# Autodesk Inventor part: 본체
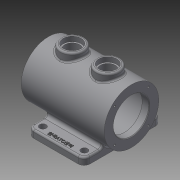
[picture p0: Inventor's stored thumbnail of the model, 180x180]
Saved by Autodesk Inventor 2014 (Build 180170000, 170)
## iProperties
Created: 2014-12
Part Number: 본체
Material: 일반
Document SubType Name: Modeling
Designer: Owner
Density: 1 g/cm^3
Appearance: 기본값
Author: Owner
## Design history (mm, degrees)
sketch "스케치1"
  geometry: L1 (-47.5, 65)-(47.5, 65); L2 (47.5, 65)-(47.5, -65); L3 (47.5, -65)-(-47.5, -65); L4 (-47.5, -65)-(-47.5, 65); 3 further points
  constraints: 8 end point, 2 midpoint, 2 parallel, 1 horizontal, 1 horizontal alignment, 1 perpendicular, 1 vertical alignment
  dimensions: "d0" = 95 distance of L1.start L1.end; "d1" = 130 distance of L1.end L2.end
extrude "돌출1" new body sketch "스케치1" distance "d2" = 12; taper "d3" = 0 deg
node "작업 평면1"
sketch "스케치2"
  geometry: L1 (0, 130)-(0, 0) reference; C1 r 46 at (-50, 65); 1 further point
  constraints: 1 centre point, 1 horizontal alignment
  dimensions: "d5" = 50 distance from line of L1 C1.centre; "d6" = 92 diameter of C1
extrude "돌출2" join sketch "스케치2" distance "d7" = 140; taper "d8" = 0 deg
node "작업 평면2"
sketch "스케치3"
  geometry: L1 (62.5, 46)-(62.5, -46) reference; C1 r 20 at (22.5, 0); C2 r 20 at (-37.5, 0); 1 further point
  constraints: 2 centre point, 2 horizontal alignment
  dimensions: "d10" = 40 distance from line of L1 C1.centre; "d11" = 60 distance of C2.centre C1.centre; "d12" = 40 diameter of C1; "d13" = 40 diameter of C2
extrude "돌출3" join sketch "스케치3" stored distance "d14" = 140; taper "d15" = 0 deg
hole "구멍1" diameter "d18" = 60; stored, may be unused: countersink angle "d22" = 90 deg, drill point angle "d24" = 0 deg; dims "d16" = 10, "d17" = 10, "d19" = 6, "d20" = 4, "d21" = 2, "d23" = 12
hole "구멍2" diameter "d27" = 75; stored, may be unused: countersink angle "d31" = 90 deg, drill point angle "d33" = 0 deg; dims "d25" = 10, "d26" = 10, "d28" = 6, "d29" = 4, "d30" = 2, "d32" = 116
hole "구멍3" diameter "d36" = 60; stored, may be unused: countersink angle "d40" = 90 deg, drill point angle "d42" = 0 deg; dims "d34" = 10, "d35" = 10, "d37" = 6, "d38" = 4, "d39" = 2, "d41" = 12
hole "구멍4" diameter "d45" = 30; stored, may be unused: countersink angle "d49" = 90 deg, drill point angle "d51" = 0 deg; dims "d43" = 10, "d44" = 10, "d46" = 6, "d47" = 4, "d48" = 2, "d50" = 8
hole "구멍5" diameter "d54" = 30; stored, may be unused: countersink angle "d58" = 90 deg, drill point angle "d60" = 0 deg; dims "d52" = 10, "d53" = 10, "d55" = 6, "d56" = 4, "d57" = 2, "d59" = 8
hole "구멍6" diameter "d63" = 25; stored, may be unused: countersink angle "d67" = 90 deg, drill point angle "d69" = 0 deg; dims "d61" = 10, "d62" = 10, "d64" = 6, "d65" = 4, "d66" = 2, "d68" = 8
hole "구멍7" diameter "d72" = 25; stored, may be unused: countersink angle "d76" = 90 deg, drill point angle "d78" = 0 deg; dims "d70" = 10, "d71" = 10, "d73" = 6, "d74" = 4, "d75" = 2, "d77" = 8
sketch "스케치4"
  geometry: L1 (0, 0)-(28.284, 28.284); L2 (0, 0)-(40, 0); C1 r 46 at (0, 0) reference; 2 further points
  constraints: 4 end point, 1 coincident, 1 equal length, 1 horizontal
  dimensions: "d79" = 40 distance of L1.start L1.end; "d80" = 45 deg angle of L2 L1
hole "구멍8" sketch "스케치4" at (28.284, 28.284) diameter "d81" = 3.242; stored, may be unused: countersink angle "d85" = 90 deg, drill point angle "d87" = 118 deg; dims "d82" = 8, "d83" = 4, "d84" = 2, "d86" = 10
sketch "스케치5"
  geometry: L1 (0, 0)-(28.284, 28.284); L2 (0, 0)-(40, 0); C1 r 46 at (0, 0) reference; 2 further points
  constraints: 4 end point, 1 coincident, 1 equal length, 1 horizontal
  dimensions: "d91" = 40 distance of L1.start L1.end; "d92" = 45 deg angle of L2 L1
hole "구멍9" sketch "스케치5" at (28.284, 28.284) diameter "d93" = 3.242; stored, may be unused: countersink angle "d97" = 90 deg, drill point angle "d99" = 118 deg; dims "d94" = 8, "d95" = 4, "d96" = 2, "d98" = 10
sketch "스케치6"
  geometry: L1 (47.5, -65)-(47.5, -25.923) reference; C1 r 5.5 at (-35, -52); C2 r 5.5 at (35, -52); C3 r 5.5 at (-35, 52); C4 r 5.5 at (35, 52); 1 further point
  constraints: 4 centre point, 3 equal radius, 2 horizontal alignment, 2 vertical alignment
  dimensions: "d103" = 70 distance of C2.centre C1.centre; "d104" = 104 distance of C2.centre C4.centre; "d105" = 52 vertical distance of C2.centre point (0, 0); "d106" = 12.5 distance from line of L1 C2.centre; "d107" = 11 diameter of C1
extrude "돌출4" cut sketch "스케치6" stored distance "d108" = 140; taper "d109" = 0 deg
fillet "모깎기1" dims "d110" = 10
fillet "모깎기2" dims "d111" = 5
fillet "모깎기3" dims "d112" = 3
fillet "모깎기4" dims "d113" = 3
sketch "스케치7"
  geometry: L1 (-37.5, -65)-(37.5, -65) reference; C1 r 5.5 at (-35, -52) reference; 2 further points
  constraints: 1 other
  dimensions: "d114" = 35 horizontal distance of point (0, -57) C1.centre; "d115" = 8 distance from line of L1 point (0, -57)
feature "엠보싱1" sketch "스케치7" dims "d0" = 95, "d1" = 130, "d15" = 0, "d116" = 1, "d117" = 0
chamfer "모따기1" distance "d118" = 1; stored, may be unused: second distance "d119" = 2, angle "d120" = 45 deg
fillet "모깎기5" dims "d121" = 3
node "솔리드1"
pattern_circular "원형 패턴1" dims angle "d89" = 360 deg
pattern_circular "원형 패턴2" dims angle "d101" = 360 deg
other parameters: "d4" = 15, "d9" = 106
